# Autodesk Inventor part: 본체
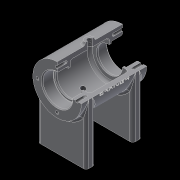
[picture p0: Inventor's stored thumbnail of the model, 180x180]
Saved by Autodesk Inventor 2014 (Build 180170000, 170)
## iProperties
Created: 2020-07
Part Number: 본체
Material: Generic
Document SubType Name: Modeling
Designer: kh
Density: 1 g/cm^3
Appearance: Default
Author: kh
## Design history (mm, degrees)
sketch "Sketch1"
  geometry: C1 r 26 at (0, 0); 1 further point
  constraints: 1 centre point, 1 coincident
  dimensions: "d0" = 52 diameter of C1
extrude "Extrusion1" new body sketch "Sketch1" stored distance "d1" = 70; taper "d2" = 0 deg
workplane "Work Plane1"
sketch "Sketch2"
  geometry: L1 (-26, 0)-(26, 0); L2 (26, 0)-(26, -64); L3 (26, -64)-(-26, -64); L4 (-26, -64)-(-26, 0); 2 further points
  constraints: 8 end point, 2 coincident, 2 parallel, 1 horizontal, 1 midpoint, 1 perpendicular
  dimensions: "d4" = 52 distance of L2.end L3.end; "d5" = 64 distance of L1.end L2.end
extrude "Extrusion2" join sketch "Sketch2" distance "d6" = 10; taper "d7" = 0 deg
mirror "Mirror1"
sketch "Sketch3"
  geometry: L1 (0, 0)-(0, -74.645); L2 (0, 0)-(8.893, -24.432); L3 (8.893, -24.432)-(9.919, -27.251); L4 (6.851, -18.824)-(1.213, -20.876); L5 (1.213, -20.876)-(4.28, -29.303); L6 (4.28, -29.303)-(9.919, -27.251); L7 (9.919, -27.251)-(6.851, -18.824); A1 r 26 centre (0, 0) between (-26, 0) and (26, 0) reference
  constraints: 15 end point, 2 parallel, 2 perpendicular, 1 collinear, 1 point on circle, 1 point on line, 1 vertical
  dimensions: "d8" = 20 deg angle of L2 L1; "d12" = 6 distance between parallel lines of L2 L5; "d83" = 29 distance from line of L1.start L6
revolve "Revolution1" sketch "Sketch3" stored, may be unused: angle "d13" = 90 deg
workplane "Work Plane3"
sketch "Sketch5"
  geometry: C1 r 5 at (0, 0); 1 further point
  constraints: 1 centre point, 1 coincident
  dimensions: "d15" = 10 diameter of C1
extrude "Extrusion3" join sketch "Sketch5" distance "d16" = 10; taper "d17" = 0 deg
sketch "Sketch6"
  geometry: L1 (0, 35)-(16, 35); L2 (16, 35)-(16, 23); L3 (16, 23)-(14, 23); L4 (14, 23)-(14, 21); L5 (14, 21)-(21, 21); L6 (21, 21)-(21, -21); L7 (21, -21)-(14, -21); L8 (14, -21)-(14, -23); L9 (14, -23)-(16, -23); L10 (16, -23)-(16, -35); L11 (16, -35)-(0, -35); L12 (0, -35)-(0, 35); L13 (26, 35)-(-26, 35) reference; L14 (-26, -35)-(26, -35) reference; 1 further point
  constraints: 24 end point, 9 parallel, 2 collinear, 1 horizontal, 1 midpoint, 1 perpendicular
  dimensions: "d18" = 28 diameter of L4 L12; "d19" = 12 distance of L1.end L2.end; "d20" = 42 distance of L5.end L6.end; "d21" = 12 distance of L9.end L10.end; "d22" = 2 distance of L7.end L8.end; "d23" = 2 distance of L3.end L4.end; "d24" = 32 diameter of L2 L12; "d25" = 42 diameter of L6 L12; "d26" = 32 diameter of L10 L12; "d27" = 28 diameter of L8 L12
revolve "Revolution2" sketch "Sketch6" stored, may be unused: angle "d28" = 90 deg
sketch "Sketch7"
  geometry: C1 r 16 at (0, 0) reference; 1 further point
  constraints: 1 vertical alignment
  dimensions: "d29" = 21 distance of point (0, 21) C1.centre
hole "Hole1" sketch "Sketch7" at (0, 21) diameter "d30" = 3.242; stored, may be unused: countersink angle "d34" = 90 deg, drill point angle "d36" = 118 deg; dims "d31" = 8, "d32" = 4, "d33" = 2, "d35" = 10
pattern_circular "Circular Pattern1" dims angle "d38" = 360 deg
mirror "Mirror2"
hole "Hole2" diameter "d42" = 5.188; stored, may be unused: countersink angle "d46" = 90 deg, drill point angle "d48" = 118 deg; dims "d40" = 10, "d41" = 10, "d43" = 8, "d44" = 4, "d45" = 2, "d47" = 10
hole "Hole3" diameter "d51" = 5.188; stored, may be unused: countersink angle "d55" = 90 deg, drill point angle "d57" = 118 deg; dims "d49" = 10, "d50" = 10, "d52" = 8, "d53" = 4, "d54" = 2, "d56" = 10
sketch "Sketch8"
  geometry: L1 (0, 10)-(52, 10) reference; 3 further points
  dimensions: "d58" = 40 distance of point (6, 5) point (46, 5); "d59" = 20 horizontal distance of point (26, -20) point (46, 5); "d60" = 5 distance from line of point (6, 5) L1
hole "Hole4" sketch "Sketch8" at (46, 5), (6, 5) diameter "d61" = 4.134; stored, may be unused: countersink angle "d65" = 90 deg, drill point angle "d67" = 118 deg; dims "d62" = 8, "d63" = 4, "d64" = 2, "d66" = 10
mirror "Mirror3"
workplane "Work Plane6"
sketch "Sketch9"
  geometry: L1 (-26, -35)-(26, -35) reference; L2 (-26, -35)-(-26, 35) reference; 2 further points
  constraints: 1 other
  dimensions: "d70" = 35 distance from line of point (0, 0) L1; "d71" = 26 distance from line of point (0, 0) L2
emboss "Emboss1" sketch "Sketch9" dims "d2" = 0, "d8" = 20 deg, "d12" = 6, "d72" = 0.5, "d73" = 0, "d83" = 29
fillet "Fillet1" dims "d74" = 2
fillet "Fillet2" dims "d75" = 0.3
fillet "Fillet3" dims "d76" = 3
chamfer "Chamfer1" distance "d77" = 1; stored, may be unused: second distance "d78" = 2, angle "d79" = 45 deg
fillet "Fillet4" dims "d80" = 3
fillet "Fillet5" dims "d81" = 3
fillet "Fillet6" dims "d82" = 3
sketch "Sketch10"
  geometry: L1 (0, 0)-(38.39, 0); L2 (38.39, 0)-(38.39, 42.957); L3 (38.39, 42.957)-(0, 42.957); L4 (0, 42.957)-(0, 0); C1 r 17 at (0, 0) reference
  constraints: 8 end point, 2 parallel, 1 horizontal, 1 perpendicular
extrude "Extrusion4" cut sketch "Sketch10" stored distance "d84" = 0; taper "d85" = 0 deg
body "Solid1"
other parameters: "d14" = 29, "d69" = -26.5
